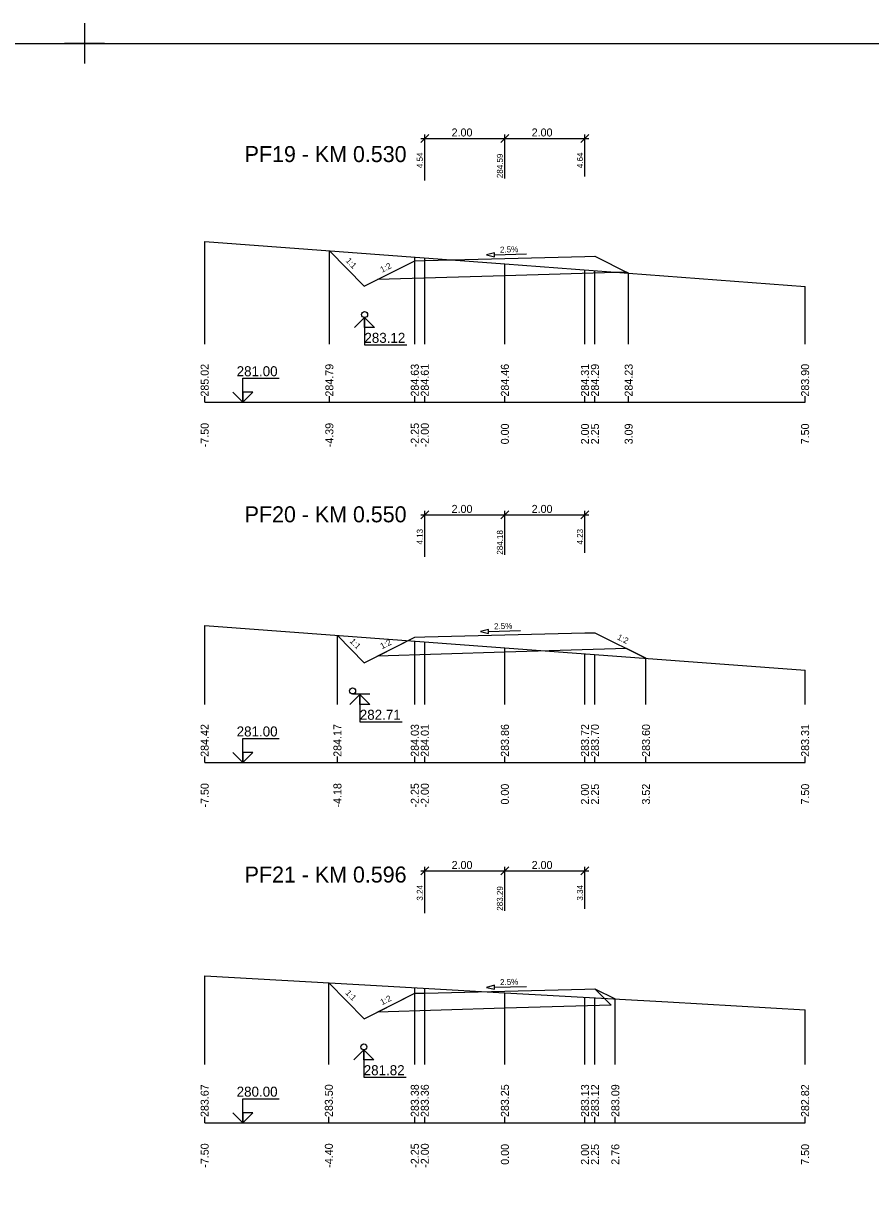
# Model space of a CAD drawing. Extents: x -5 to 1895, y -2 to 602.
# Drawn here: x 1244.7 to 1456.4, y 310.3 to 601.7 of the extents above; entities that cross this region are included whole.
import ezdxf

# ---------------------------------------------------------------- set-up
doc = ezdxf.new("R2010")
doc.units = 0
for name, color, linetype in [('KOTA', 7, 'Continuous'), ('KOTA_DELKY', 7, 'Continuous'), ('KOTA_DELKY_CONT', 7, 'Continuous'), ('KRIZENI', 7, 'Continuous'), ('NS_TELESO_VOZOVKY', 7, 'Continuous'), ('NS_V_PF', 7, 'Continuous'), ('REZY_PF_PUVODNI', 7, 'Continuous'), ('SESTAVY_REZU_PF', 7, 'Continuous'), ('SKLON', 7, 'Continuous'), ('SVK', 7, 'Continuous')]:
    doc.layers.add(name, color=color, linetype=linetype)

msp = doc.modelspace()

# ---------------------------------------------------------------- linework, layer by layer
for p, q in [((1260, 601.67), (1260, 591.67)), ((1260, 601.67), (1260, 591.67)), ((1260, 601.67), (1260, 591.67)), ((1260, 601.67), (1260, 591.67)), ((1260, 601.67), (1260, 591.67)), ((1260, 601.67), (1260, 591.67)), ((1260, 601.67), (1260, 591.67)), ((1260, 601.67), (1260, 591.67)), ((1260, 601.67), (1260, 591.67)), ((1260, 601.67), (1260, 591.67)), ((1260, 601.67), (1260, 591.67)), ((1260, 601.67), (1260, 591.67)), ((1260, 601.67), (1260, 591.67)), ((1260, 601.67), (1260, 591.67)), ((1260, 601.67), (1260, 591.67)), ((1260, 601.67), (1260, 591.67)), ((1260, 601.67), (1260, 591.67)), ((1260, 601.67), (1260, 591.67)), ((1260, 601.67), (1260, 591.67)), ((1260, 601.67), (1260, 591.67)), ((1260, 601.67), (1260, 591.67)), ((1260, 601.67), (1260, 591.67)), ((1260, 601.67), (1260, 591.67)), ((1260, 601.67), (1260, 591.67)), ((1260, 601.67), (1260, 591.67)), ((1260, 601.67), (1260, 591.67)), ((1260, 601.67), (1260, 591.67)), ((1260, 601.67), (1260, 591.67)), ((1260, 601.67), (1260, 591.67)), ((1260, 601.67), (1260, 591.67)), ((1260, 601.67), (1260, 591.67)), ((1260, 601.67), (1260, 591.67)), ((1260, 601.67), (1260, 591.67)), ((1260, 601.67), (1260, 591.67)), ((1260, 601.67), (1260, 591.67)), ((1260, 601.67), (1260, 591.67)), ((1260, 601.67), (1260, 591.67)), ((1260, 601.67), (1260, 591.67)), ((1260, 601.67), (1260, 591.67)), ((1260, 601.67), (1260, 591.67)), ((1260, 601.67), (1260, 591.67)), ((1260, 601.67), (1260, 591.67)), ((1260, 601.67), (1260, 591.67)), ((1260, 601.67), (1260, 591.67)), ((1260, 601.67), (1260, 591.67)), ((1260, 601.67), (1260, 591.67)), ((1260, 601.67), (1260, 591.67)), ((1260, 601.67), (1260, 591.67)), ((1260, 601.67), (1260, 591.67)), ((1260, 601.67), (1260, 591.67)), ((1260, 601.67), (1260, 591.67)), ((1260, 601.67), (1260, 591.67)), ((1260, 601.67), (1260, 591.67)), ((1260, 601.67), (1260, 591.67)), ((1265, 596.67), (1255, 596.67)), ((1265, 596.67), (1255, 596.67)), ((1265, 596.67), (1255, 596.67)), ((1265, 596.67), (1255, 596.67)), ((1265, 596.67), (1255, 596.67)), ((1265, 596.67), (1255, 596.67)), ((1265, 596.67), (1255, 596.67)), ((1265, 596.67), (1255, 596.67)), ((1265, 596.67), (1255, 596.67)), ((1265, 596.67), (1255, 596.67)), ((1265, 596.67), (1255, 596.67)), ((1265, 596.67), (1255, 596.67)), ((1265, 596.67), (1255, 596.67)), ((1265, 596.67), (1255, 596.67)), ((1265, 596.67), (1255, 596.67)), ((1265, 596.67), (1255, 596.67)), ((1265, 596.67), (1255, 596.67)), ((1265, 596.67), (1255, 596.67)), ((1265, 596.67), (1255, 596.67)), ((1265, 596.67), (1255, 596.67)), ((1265, 596.67), (1255, 596.67)), ((1265, 596.67), (1255, 596.67)), ((1265, 596.67), (1255, 596.67)), ((1265, 596.67), (1255, 596.67)), ((1265, 596.67), (1255, 596.67)), ((1265, 596.67), (1255, 596.67)), ((1265, 596.67), (1255, 596.67)), ((1265, 596.67), (1255, 596.67)), ((1265, 596.67), (1255, 596.67)), ((1265, 596.67), (1255, 596.67)), ((1265, 596.67), (1255, 596.67)), ((1265, 596.67), (1255, 596.67)), ((1265, 596.67), (1255, 596.67)), ((1265, 596.67), (1255, 596.67)), ((1265, 596.67), (1255, 596.67)), ((1265, 596.67), (1255, 596.67)), ((1265, 596.67), (1255, 596.67)), ((1265, 596.67), (1255, 596.67)), ((1265, 596.67), (1255, 596.67)), ((1265, 596.67), (1255, 596.67)), ((1265, 596.67), (1255, 596.67)), ((1265, 596.67), (1255, 596.67)), ((1265, 596.67), (1255, 596.67)), ((1265, 596.67), (1255, 596.67)), ((1265, 596.67), (1255, 596.67)), ((1265, 596.67), (1255, 596.67)), ((1265, 596.67), (1255, 596.67)), ((1265, 596.67), (1255, 596.67)), ((1265, 596.67), (1255, 596.67)), ((1265, 596.67), (1255, 596.67)), ((1265, 596.67), (1255, 596.67)), ((1265, 596.67), (1255, 596.67)), ((1265, 596.67), (1255, 596.67)), ((1265, 596.67), (1255, 596.67))]:
    msp.add_line(p, q)
msp.add_lwpolyline([(0, 596.67), (1890, 596.67), (1890, 2.67), (0, 2.67)], close=True)
at = {"layer": 'KOTA'}
for points in [[(1329.95, 528.16), (1327.45, 525.66), (1329.95, 528.16), (1329.95, 521.34), (1340.49, 521.34)], [(1329.95, 528.16), (1332.45, 525.66), (1329.95, 525.66), (1329.95, 528.16)], [(1329.95, 528.16), (1332.45, 525.66), (1329.95, 525.66)], [(1299.57, 507), (1297.07, 509.5), (1299.57, 507), (1299.57, 513), (1308.57, 513)], [(1299.57, 507), (1302.07, 509.5), (1299.57, 509.5), (1299.57, 507)], [(1299.57, 507), (1302.07, 509.5), (1299.57, 509.5)], [(1328.79, 433.99), (1326.29, 431.49), (1328.79, 433.99), (1328.79, 427.17), (1339.33, 427.17)], [(1326.95, 434.11), (1331.22, 434.11)], [(1328.79, 433.99), (1331.29, 431.49), (1328.79, 431.49), (1328.79, 433.99)], [(1328.79, 433.99), (1331.29, 431.49), (1328.79, 431.49)], [(1299.57, 417), (1297.07, 419.5), (1299.57, 417), (1299.57, 423), (1308.57, 423)], [(1299.57, 417), (1302.07, 419.5), (1299.57, 419.5), (1299.57, 417)], [(1299.57, 417), (1302.07, 419.5), (1299.57, 419.5)], [(1329.77, 345.19), (1327.27, 342.69), (1329.77, 345.19), (1329.77, 338.37), (1340.31, 338.37)], [(1329.77, 345.19), (1332.27, 342.69), (1329.77, 342.69), (1329.77, 345.19)], [(1329.77, 345.19), (1332.27, 342.69), (1329.77, 342.69)], [(1299.57, 327), (1297.07, 329.5), (1299.57, 327), (1299.57, 333), (1308.57, 333)], [(1299.57, 327), (1302.07, 329.5), (1299.57, 329.5), (1299.57, 327)], [(1299.57, 327), (1302.07, 329.5), (1299.57, 329.5)]]:
    msp.add_lwpolyline(points, dxfattribs=at)
at = {"layer": 'KOTA_DELKY'}
for points in [[(1344, 571.9), (1346, 573.9)], [(1344, 572.9), (1366, 572.9)], [(1345, 562.4), (1345, 573.9)], [(1364, 571.9), (1366, 573.9)], [(1364, 571.9), (1366, 573.9)], [(1364, 572.9), (1386, 572.9)], [(1365, 562.9), (1365, 573.9)], [(1365, 562.9), (1365, 573.9)], [(1384, 571.9), (1386, 573.9)], [(1385, 563.4), (1385, 573.9)], [(1344, 477.85), (1346, 479.85)], [(1344, 478.85), (1366, 478.85)], [(1345, 468.35), (1345, 479.85)], [(1364, 477.85), (1366, 479.85)], [(1364, 477.85), (1366, 479.85)], [(1364, 478.85), (1386, 478.85)], [(1365, 468.85), (1365, 479.85)], [(1365, 468.85), (1365, 479.85)], [(1384, 477.85), (1386, 479.85)], [(1385, 469.35), (1385, 479.85)], [(1344, 388.89), (1346, 390.89)], [(1345, 379.39), (1345, 390.89)], [(1364, 388.89), (1366, 390.89)], [(1364, 388.89), (1366, 390.89)], [(1365, 379.89), (1365, 390.89)], [(1365, 379.89), (1365, 390.89)], [(1384, 388.89), (1386, 390.89)], [(1385, 380.39), (1385, 390.89)], [(1344, 389.89), (1366, 389.89)], [(1364, 389.89), (1386, 389.89)]]:
    msp.add_lwpolyline(points, dxfattribs=at)
at = {"layer": 'KRIZENI'}
for centre in [(1329.95, 528.91), (1326.95, 434.86), (1329.77, 345.94)]:
    msp.add_circle(centre, 0.75, dxfattribs=at)
at = {"layer": 'NS_TELESO_VOZOVKY'}
for points in [[(1365, 542.9), (1385, 543.4), (1387.5, 543.47), (1395.92, 539.26), (1395.4, 539.52), (1365, 538.6), (1333.2, 537.65), (1342.5, 542.34), (1345, 542.4), (1365, 542.9)], [(1365, 448.85), (1385, 449.35), (1387.5, 449.41), (1400.25, 443.04), (1395.4, 445.46), (1365, 444.55), (1333.2, 443.59), (1342.5, 448.28), (1345, 448.35), (1365, 448.85)], [(1365, 359.89), (1385, 360.39), (1387.5, 360.45), (1391.57, 356.38), (1365, 355.59), (1333.2, 354.63), (1342.5, 359.32), (1345, 359.39), (1365, 359.89)]]:
    msp.add_lwpolyline(points, dxfattribs=at)
at = {"layer": 'NS_V_PF'}
for points in [[(1321.15, 544.86), (1329.87, 535.97), (1342.5, 542.34), (1345, 542.4), (1365, 542.9), (1385, 543.4), (1387.5, 543.47), (1395.92, 539.26)], [(1323.17, 448.74), (1329.87, 441.91), (1342.5, 448.28), (1345, 448.35), (1365, 448.85), (1385, 449.35), (1387.5, 449.41), (1400.25, 443.04)], [(1321.02, 361.97), (1329.87, 352.95), (1342.5, 359.32), (1345, 359.39), (1365, 359.89), (1385, 360.39), (1387.5, 360.45), (1392.59, 357.91)]]:
    msp.add_lwpolyline(points, dxfattribs=at)
at = {"layer": 'REZY_PF_PUVODNI'}
for points in [[(1290, 547.2), (1365, 541.58), (1365, 541.58), (1440, 535.95)], [(1290, 451.2), (1365, 445.65), (1440, 440.09)], [(1290, 363.73), (1328.55, 361.55), (1365, 359.48), (1405.74, 357.16), (1440, 355.22)]]:
    msp.add_lwpolyline(points, dxfattribs=at)
at = {"layer": 'SESTAVY_REZU_PF'}
for points in [[(1290, 507), (1440, 507)], [(1290, 417), (1440, 417)], [(1290, 327), (1440, 327)]]:
    msp.add_lwpolyline(points, dxfattribs=at)
at = {"layer": 'SKLON'}
for points in [[(1362.39, 544.34), (1360.4, 543.79), (1362.41, 543.34)], [(1360.9, 450.24), (1358.91, 449.69), (1360.92, 449.24)], [(1362.39, 361.32), (1360.4, 360.77), (1362.41, 360.32)]]:
    msp.add_lwpolyline(points, close=True, dxfattribs=at)
for points in [[(1362.39, 544.34), (1360.4, 543.79), (1362.41, 543.34), (1362.39, 544.34)], [(1362.4, 543.84), (1370.4, 544.04)], [(1360.9, 450.24), (1358.91, 449.69), (1360.92, 449.24), (1360.9, 450.24)], [(1360.91, 449.74), (1368.91, 449.94)], [(1362.39, 361.32), (1360.4, 360.77), (1362.41, 360.32), (1362.39, 361.32)], [(1362.4, 360.82), (1370.4, 361.02)]]:
    msp.add_lwpolyline(points, dxfattribs=at)
at = {"layer": 'SVK'}
for points in [[(1290, 521.5), (1290, 547.2)], [(1321.15, 521.5), (1321.15, 544.86)], [(1342.5, 521.5), (1342.5, 543.26)], [(1345, 521.5), (1345, 543.08)], [(1365, 521.5), (1365, 541.58)], [(1385, 521.5), (1385, 540.08)], [(1387.5, 521.5), (1387.5, 539.89)], [(1395.92, 521.5), (1395.92, 539.26)], [(1440, 521.5), (1440, 535.95)], [(1290, 507), (1290, 508.5)], [(1321.15, 507), (1321.15, 508.5)], [(1342.5, 507), (1342.5, 508.5)], [(1345, 507), (1345, 508.5)], [(1365, 507), (1365, 508.5)], [(1385, 507), (1385, 508.5)], [(1387.5, 507), (1387.5, 508.5)], [(1395.92, 507), (1395.92, 508.5)], [(1440, 507), (1440, 508.5)], [(1290, 431.5), (1290, 451.2)], [(1323.17, 431.5), (1323.17, 448.74)], [(1342.5, 431.5), (1342.5, 447.31)], [(1345, 431.5), (1345, 447.13)], [(1365, 431.5), (1365, 445.65)], [(1385, 431.5), (1385, 444.16)], [(1387.5, 431.5), (1387.5, 443.98)], [(1400.25, 431.5), (1400.25, 443.04)], [(1440, 431.5), (1440, 440.09)], [(1290, 417), (1290, 418.5)], [(1323.17, 417), (1323.17, 418.5)], [(1342.5, 417), (1342.5, 418.5)], [(1345, 417), (1345, 418.5)], [(1365, 417), (1365, 418.5)], [(1385, 417), (1385, 418.5)], [(1387.5, 417), (1387.5, 418.5)], [(1400.25, 417), (1400.25, 418.5)], [(1440, 417), (1440, 418.5)], [(1290, 341.5), (1290, 363.73)], [(1321.02, 341.5), (1321.02, 361.97)], [(1342.5, 341.5), (1342.5, 360.76)], [(1345, 341.5), (1345, 360.61)], [(1365, 341.5), (1365, 359.48)], [(1385, 341.5), (1385, 358.34)], [(1387.5, 341.5), (1387.5, 358.19)], [(1392.59, 341.5), (1392.59, 357.91)], [(1440, 341.5), (1440, 355.22)], [(1290, 327), (1290, 328.5)], [(1321.02, 327), (1321.02, 328.5)], [(1342.5, 327), (1342.5, 328.5)], [(1345, 327), (1345, 328.5)], [(1365, 327), (1365, 328.5)], [(1385, 327), (1385, 328.5)], [(1387.5, 327), (1387.5, 328.5)], [(1392.59, 327), (1392.59, 328.5)], [(1440, 327), (1440, 328.5)]]:
    msp.add_lwpolyline(points, dxfattribs=at)

# ---------------------------------------------------------------- texts
at = {"layer": 'KOTA'}
for s, p in [('283.12', (1329.9, 521.84)), ('281.00', (1297.99, 513.5)), ('282.71', (1328.75, 427.67)), ('281.00', (1297.99, 423.5)), ('281.82', (1329.73, 338.87)), ('280.00', (1297.99, 333.5))]:
    msp.add_text(s, height=2.5, dxfattribs=at).set_placement(p)
at = {"layer": 'KOTA_DELKY'}
for p in [(1351.69, 573.4), (1371.69, 573.4), (1351.69, 479.35), (1371.69, 479.35), (1351.69, 390.39), (1371.69, 390.39)]:
    msp.add_text('2.00', height=2, dxfattribs=at).set_placement(p)
at = {"layer": 'KOTA_DELKY_CONT'}
for s, p in [('4.54', (1344.5, 565.49)), ('284.59', (1364.5, 562.98)), ('4.64', (1384.5, 565.49)), ('4.13', (1344.5, 471.44)), ('4.23', (1384.5, 471.44)), ('284.18', (1364.5, 468.92)), ('3.24', (1344.5, 382.48)), ('283.29', (1364.5, 379.96)), ('3.34', (1384.5, 382.48))]:
    msp.add_text(s, height=1.5, rotation=90, dxfattribs=at).set_placement(p)
at = {"layer": 'SESTAVY_REZU_PF'}
for s, p in [('PF19 - KM 0.530', (1300, 567)), ('PF20 - KM 0.550', (1300, 477)), ('PF21 - KM 0.596', (1300, 387))]:
    msp.add_text(s, height=4, dxfattribs=at).set_placement(p)
at = {"layer": 'SKLON'}
for s, rotation, p in [('2.5%', 1.4321, (1363.8, 544.37)), ('1:1', 314.4213, (1325.12, 542.24)), ('1:2', 26.7649, (1334.32, 539.34)), ('2.5%', 1.4321, (1362.31, 450.28)), ('1:2', 333.4349, (1392.91, 447.82)), ('1:1', 314.4213, (1326.13, 447.15)), ('1:2', 26.7649, (1334.32, 445.28)), ('2.5%', 1.4321, (1363.8, 361.36)), ('1:1', 314.4213, (1325.05, 359.29)), ('1:2', 26.7649, (1334.32, 356.32))]:
    msp.add_text(s, height=1.5, rotation=rotation, dxfattribs=at).set_placement(p)
at = {"layer": 'SVK'}
for s, p in [(' 285.02', (1291, 507.67)), (' 284.79', (1322.15, 507.67)), (' 284.63', (1343.5, 507.67)), (' 284.61', (1346, 507.67)), (' 284.46', (1366, 507.67)), (' 284.31', (1386, 507.67)), (' 284.29', (1388.5, 507.67)), (' 284.23', (1396.92, 507.67)), (' 283.90', (1441, 507.67)), (' -7.50', (1291, 495)), (' -4.39', (1322.15, 495)), (' -2.25', (1343.5, 495)), (' -2.00', (1346, 495)), ('  0.00', (1366, 495)), ('  2.00', (1386, 495)), ('  2.25', (1388.5, 495)), ('  3.09', (1396.92, 495)), ('  7.50', (1441, 495)), (' 284.42', (1291, 417.67)), (' 284.17', (1324.17, 417.67)), (' 284.03', (1343.5, 417.67)), (' 284.01', (1346, 417.67)), (' 283.86', (1366, 417.67)), (' 283.72', (1386, 417.67)), (' 283.70', (1388.5, 417.67)), (' 283.60', (1401.25, 417.67)), (' 283.31', (1441, 417.67)), (' -7.50', (1291, 405)), (' -4.18', (1324.17, 405)), (' -2.25', (1343.5, 405)), (' -2.00', (1346, 405)), ('  0.00', (1366, 405)), ('  2.00', (1386, 405)), ('  2.25', (1388.5, 405)), ('  3.52', (1401.25, 405)), ('  7.50', (1441, 405)), (' 283.67', (1291, 327.67)), (' 283.50', (1322.02, 327.67)), (' 283.38', (1343.5, 327.67)), (' 283.36', (1346, 327.67)), (' 283.25', (1366, 327.67)), (' 283.13', (1386, 327.67)), (' 283.12', (1388.5, 327.67)), (' 283.09', (1393.59, 327.67)), (' 282.82', (1441, 327.67)), (' -7.50', (1291, 315)), (' -4.40', (1322.02, 315)), (' -2.25', (1343.5, 315)), (' -2.00', (1346, 315)), ('  0.00', (1366, 315)), ('  2.00', (1386, 315)), ('  2.25', (1388.5, 315)), ('  2.76', (1393.59, 315)), ('  7.50', (1441, 315))]:
    msp.add_text(s, height=2, rotation=90, dxfattribs=at).set_placement(p)

doc.saveas('drawing.dxf')
